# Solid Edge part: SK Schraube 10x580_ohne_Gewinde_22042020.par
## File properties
Author: fknapp
Template: Normal.par
Last saved by: fknapp
Revision: 33
Application: Solid Edge
Username: fknapp
Material: Aluminium
Genauigkeit: 0,99
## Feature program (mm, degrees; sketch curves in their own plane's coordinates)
sketch for "unnamed RevolvedProtrusion 1" plane through (0, 0, 0) normal (0, 0, 1) x-axis (1, 0, 0)
  line (0, 54) -> (9, 54)
  line (9, 54) -> (9, 53)
  line (9, 53) -> (5, 49)
  line (5, 49) -> (5, 46.3)
  line (5, 46.3) -> (4.7548, 46.3)
  arc centre (4.7548, 44.6952) radius 1.6048 from (4.7548, 46.3) to (3.15, 44.6952) ccw
  line (3.15, 44.6952) -> (3.15, 42)
  line (3.15, 42) -> (5, 42)
  line (5, -513) -> (5, 42)
  line (0.5, -526) -> (5, -513)
  line (0, -526) -> (0.5, -526)
revolve "unnamed RevolvedProtrusion 1" add full turn 360 deg about sketch line (0, 54) -> (0, -526)
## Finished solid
Body 1: solid body, 11 faces, 10 edges, 0 vertices.
  Faces by surface: cylinder 4, plane 4, cone 2, torus 1
  Edges by curve: circle 10
Bounding box of the edges (mm; curved faces can reach further): 18.000 x 580.000 x 18.000, from (-9, -526, -9) to (9, 54, 9).
Cylindrical faces by radius (mm): R3.15 x1, R5 x2, R9 x1
Conical faces (half-angle, radius in mm at the cone's reference point): 19.0935 deg R5 x1, 45 deg R9 x1
Toroidal faces (ring radius, tube radius in mm): R4.7548 r1.6048 x1
Planar faces by outward normal: +y 2, -y 2
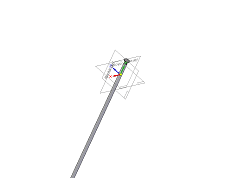
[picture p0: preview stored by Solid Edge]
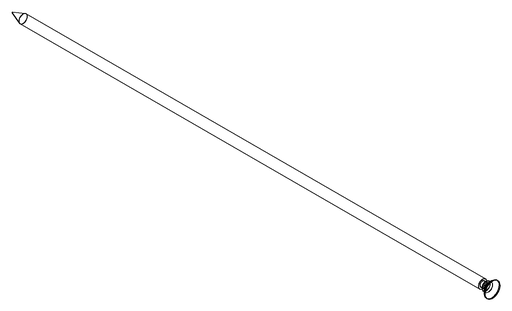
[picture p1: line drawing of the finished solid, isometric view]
